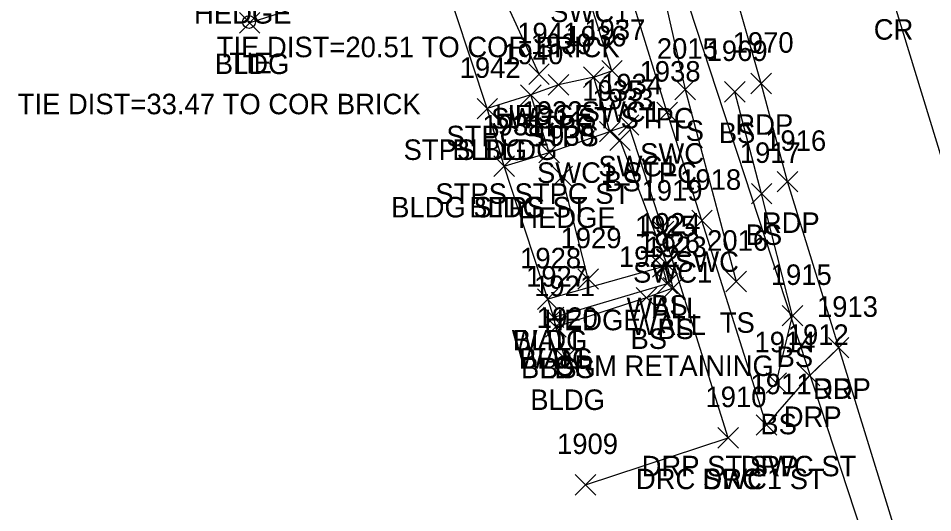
# Model space of a CAD drawing. Extents: x 1620157 to 1620595, y 115111 to 117885.
# Drawn here: x 1620162.6 to 1620251.8, y 115651.9 to 115700.1 of the extents above; entities that cross this region are included whole.
import ezdxf

# ---------------------------------------------------------------- set-up
doc = ezdxf.new("R2010")
doc.units = 0
for name, color, linetype in [('C_A', 7, 'Continuous'), ('C_C', 7, 'Continuous'), ('CBP', 7, 'Continuous'), ('DCP', 7, 'Continuous'), ('L_A', 7, 'Continuous'), ('L_C', 7, 'Continuous'), ('L_I', 7, 'Continuous'), ('L_TIC', 7, 'Continuous'), ('LAHR', 7, 'Continuous'), ('LBC', 7, 'Continuous'), ('LBF', 7, 'Continuous'), ('LELB', 7, 'Continuous'), ('LW', 7, 'Continuous'), ('P_A', 7, 'Continuous'), ('P_I', 7, 'Continuous'), ('P_TIC', 7, 'Continuous'), ('PET', 7, 'Continuous'), ('PRC', 7, 'Continuous'), ('R_A', 7, 'Continuous'), ('R_I', 7, 'Continuous'), ('R_TIC', 7, 'Continuous'), ('RDP', 7, 'Continuous'), ('RSW', 7, 'Continuous')]:
    doc.layers.add(name, color=color, linetype=linetype)

msp = doc.modelspace()

# ---------------------------------------------------------------- linework, layer by layer
at = {"layer": 'CBP'}
for radius in [0.625, 0.0833]:
    msp.add_circle((1620185.129, 115699.764), radius, dxfattribs=at)
at = {"layer": 'DCP'}
msp.add_lwpolyline([(1620265.107, 115588.482), (1620223.378, 115715.616)], dxfattribs=at)
at = {"layer": 'L_TIC'}
for points in [[(1620184.195, 115698.683), (1620186.195, 115700.683)], [(1620186.195, 115698.683), (1620184.195, 115700.683)], [(1620212.417, 115693.681), (1620214.417, 115695.681)], [(1620214.417, 115693.681), (1620212.417, 115695.681)], [(1620217.753, 115693.378), (1620219.753, 115695.378)], [(1620219.753, 115693.378), (1620217.753, 115695.378)], [(1620214.313, 115692.628), (1620216.313, 115694.628)], [(1620216.313, 115692.628), (1620214.313, 115694.628)], [(1620226.682, 115692.172), (1620228.682, 115694.172)], [(1620228.682, 115692.172), (1620226.682, 115694.172)], [(1620231.511, 115691.955), (1620233.511, 115693.955)], [(1620233.511, 115691.955), (1620231.511, 115693.955)], [(1620211.618, 115691.643), (1620213.618, 115693.643)], [(1620213.618, 115691.643), (1620211.618, 115693.643)], [(1620211.618, 115691.643), (1620213.618, 115693.643)], [(1620213.618, 115691.643), (1620211.618, 115693.643)], [(1620207.37, 115690.31), (1620209.37, 115692.31)], [(1620209.37, 115690.31), (1620207.37, 115692.31)], [(1620207.37, 115690.31), (1620209.37, 115692.31)], [(1620209.37, 115690.31), (1620207.37, 115692.31)], [(1620219.331, 115688.074), (1620221.331, 115690.074)], [(1620221.331, 115688.074), (1620219.331, 115690.074)], [(1620220.32, 115687.244), (1620222.32, 115689.244)], [(1620222.32, 115687.244), (1620220.32, 115689.244)], [(1620213.414, 115686.031), (1620215.414, 115688.031)], [(1620215.414, 115686.031), (1620213.414, 115688.031)], [(1620213.414, 115686.031), (1620215.414, 115688.031)], [(1620215.414, 115686.031), (1620213.414, 115688.031)], [(1620209.026, 115684.705), (1620211.026, 115686.705)], [(1620211.026, 115684.705), (1620209.026, 115686.705)], [(1620209.026, 115684.705), (1620211.026, 115686.705)], [(1620211.026, 115684.705), (1620209.026, 115686.705)], [(1620214.691, 115683.69), (1620216.691, 115685.69)], [(1620216.691, 115683.69), (1620214.691, 115685.69)], [(1620234.13, 115682.022), (1620236.13, 115684.022)], [(1620236.13, 115682.022), (1620234.13, 115684.022)], [(1620224.478, 115674.876), (1620226.478, 115676.876)], [(1620226.478, 115674.876), (1620224.478, 115676.876)], [(1620224.478, 115674.876), (1620226.478, 115676.876)], [(1620226.478, 115674.876), (1620224.478, 115676.876)], [(1620224.906, 115675.132), (1620226.906, 115677.132)], [(1620226.906, 115675.132), (1620224.906, 115677.132)], [(1620217.217, 115673.706), (1620219.217, 115675.706)], [(1620219.217, 115673.706), (1620217.217, 115675.706)], [(1620224.923, 115673.246), (1620226.923, 115675.246)], [(1620226.923, 115673.246), (1620224.923, 115675.246)], [(1620231.641, 115673.457), (1620233.641, 115675.457)], [(1620233.641, 115673.457), (1620231.641, 115675.457)], [(1620225.517, 115672.845), (1620227.517, 115674.845)], [(1620227.517, 115672.845), (1620225.517, 115674.845)], [(1620213.268, 115671.742), (1620215.268, 115673.742)], [(1620215.268, 115671.742), (1620213.268, 115673.742)], [(1620213.268, 115671.742), (1620215.268, 115673.742)], [(1620215.268, 115671.742), (1620213.268, 115673.742)], [(1620222.902, 115671.883), (1620224.902, 115673.883)], [(1620224.902, 115671.883), (1620222.902, 115673.883)], [(1620213.849, 115669.959), (1620215.849, 115671.959)], [(1620215.849, 115669.959), (1620213.849, 115671.959)], [(1620213.849, 115669.959), (1620215.849, 115671.959)], [(1620215.849, 115669.959), (1620213.849, 115671.959)], [(1620237.148, 115670.123), (1620239.148, 115672.123)], [(1620239.148, 115670.123), (1620237.148, 115672.123)], [(1620214.066, 115669.033), (1620216.066, 115671.033)], [(1620216.066, 115669.033), (1620214.066, 115671.033)], [(1620214.066, 115669.033), (1620216.066, 115671.033)], [(1620216.066, 115669.033), (1620214.066, 115671.033)], [(1620214.975, 115665.935), (1620216.975, 115667.935)], [(1620216.975, 115665.935), (1620214.975, 115667.935)], [(1620235.562, 115663.561), (1620237.562, 115665.561)], [(1620237.562, 115663.561), (1620235.562, 115665.561)]]:
    msp.add_lwpolyline(points, dxfattribs=at)
at = {"layer": 'LAHR'}
for points in [[(1620213.417, 115694.681), (1620206.467, 115709.825), (1620184.063, 115704.598)], [(1620218.217, 115674.706), (1620215.691, 115684.69)]]:
    msp.add_lwpolyline(points, dxfattribs=at)
at = {"layer": 'LBC'}
msp.add_lwpolyline([(1620215.975, 115666.935), (1620215.066, 115670.033), (1620214.849, 115670.959), (1620214.268, 115672.742), (1620210.026, 115685.705), (1620208.37, 115691.31), (1620203.654, 115705.592), (1620185.195, 115699.683)], dxfattribs=at)
at = {"layer": 'LBF'}
for points in [[(1620214.414, 115687.031), (1620220.331, 115689.074), (1620218.753, 115694.378), (1620215.313, 115693.628), (1620212.618, 115692.643)], [(1620210.026, 115685.705), (1620214.414, 115687.031), (1620212.618, 115692.643), (1620208.37, 115691.31)]]:
    msp.add_lwpolyline(points, dxfattribs=at)
at = {"layer": 'LELB'}
for points in [[(1620197.795, 115734.316), (1620202.944, 115732.819), (1620211.98, 115722.576), (1620224.178, 115708.712), (1620227.682, 115693.172), (1620232.641, 115674.457)], [(1620236.562, 115664.561), (1620238.148, 115671.123), (1620235.13, 115683.022), (1620232.511, 115692.955)], [(1620215.066, 115670.033), (1620223.902, 115672.883), (1620226.517, 115673.845), (1620225.906, 115676.132), (1620221.32, 115688.244)]]:
    msp.add_lwpolyline(points, dxfattribs=at)
at = {"layer": 'LW'}
for points in [[(1620225.478, 115675.876), (1620214.268, 115672.742)], [(1620225.478, 115675.876), (1620225.923, 115674.246), (1620214.849, 115670.959)]]:
    msp.add_lwpolyline(points, dxfattribs=at)
at = {"layer": 'P_TIC'}
for points in [[(1620234.083, 115692.763), (1620236.083, 115694.763)], [(1620236.083, 115692.763), (1620234.083, 115694.763)], [(1620236.662, 115683.194), (1620238.662, 115685.194)], [(1620238.662, 115683.194), (1620236.662, 115685.194)], [(1620241.654, 115667.014), (1620243.654, 115669.014)], [(1620243.654, 115667.014), (1620241.654, 115669.014)]]:
    msp.add_lwpolyline(points, dxfattribs=at)
at = {"layer": 'PET'}
msp.add_lwpolyline([(1620320.138, 115439.395), (1620314.873, 115455.055), (1620309.06, 115464.385), (1620304.219, 115479.395), (1620297.094, 115496.088), (1620293.948, 115506.925), (1620292.02, 115512.471), (1620283.673, 115536.019), (1620274.577, 115564.814), (1620268.484, 115584.523), (1620253.11, 115635.23), (1620250.119, 115643.884), (1620242.654, 115668.014), (1620237.662, 115684.194), (1620235.083, 115693.763), (1620231.193, 115707.415), (1620225.409, 115727.426), (1620211.93, 115771.954), (1620203.83, 115799.038), (1620193.365, 115837.216)], dxfattribs=at)
at = {"layer": 'PRC'}
msp.add_lwpolyline([(1620328.083, 115447.457), (1620322.143, 115466.609), (1620311.316, 115499.812), (1620303.781, 115522.909), (1620294.725, 115551.741), (1620279.311, 115600.233), (1620271.119, 115626.45), (1620257.914, 115669.486), (1620247.637, 115703.034), (1620242.452, 115719.653), (1620232.976, 115752.347), (1620223.662, 115784.044), (1620214.136, 115816.154), (1620207.469, 115841.181)], dxfattribs=at)
at = {"layer": 'R_TIC'}
for points in [[(1620219.531, 115694.011), (1620221.531, 115696.011)], [(1620221.531, 115694.011), (1620219.531, 115696.011)], [(1620217.753, 115693.378), (1620219.753, 115695.378)], [(1620219.753, 115693.378), (1620217.753, 115695.378)], [(1620224.918, 115689.945), (1620226.918, 115691.945)], [(1620226.918, 115689.945), (1620224.918, 115691.945)], [(1620221.168, 115688.711), (1620223.168, 115690.711)], [(1620223.168, 115688.711), (1620221.168, 115690.711)], [(1620219.331, 115688.074), (1620221.331, 115690.074)], [(1620221.331, 115688.074), (1620219.331, 115690.074)], [(1620228.313, 115679.398), (1620230.313, 115681.398)], [(1620230.313, 115679.398), (1620228.313, 115681.398)], [(1620224.553, 115678.345), (1620226.553, 115680.345)], [(1620226.553, 115678.345), (1620224.553, 115680.345)], [(1620241.654, 115667.014), (1620243.654, 115669.014)], [(1620243.654, 115667.014), (1620241.654, 115669.014)], [(1620238.804, 115664.278), (1620240.804, 115666.278)], [(1620240.804, 115664.278), (1620238.804, 115666.278)], [(1620234.608, 115659.465), (1620236.608, 115661.465)], [(1620236.608, 115659.465), (1620234.608, 115661.465)], [(1620234.608, 115659.465), (1620236.608, 115661.465)], [(1620236.608, 115659.465), (1620234.608, 115661.465)], [(1620230.868, 115658.214), (1620232.868, 115660.214)], [(1620232.868, 115658.214), (1620230.868, 115660.214)], [(1620230.868, 115658.214), (1620232.868, 115660.214)], [(1620232.868, 115658.214), (1620230.868, 115660.214)], [(1620216.957, 115653.638), (1620218.957, 115655.638)], [(1620218.957, 115653.638), (1620216.957, 115655.638)]]:
    msp.add_lwpolyline(points, dxfattribs=at)
at = {"layer": 'RDP'}
for points in [[(1620235.608, 115660.465), (1620239.804, 115665.278), (1620242.654, 115668.014)], [(1620217.957, 115654.638), (1620231.868, 115659.214)]]:
    msp.add_lwpolyline(points, dxfattribs=at)
at = {"layer": 'RSW'}
for points in [[(1620235.608, 115660.465), (1620229.313, 115680.398), (1620225.918, 115690.945), (1620221.039, 115706.713), (1620220.247, 115708.993), (1620218.98, 115710.722), (1620216.243, 115713.35), (1620201.579, 115727.899), (1620197.914, 115731.583), (1620194.509, 115734.738), (1620191.974, 115731.835), (1620193.114, 115730.36), (1620193.386, 115728.404), (1620192.886, 115726.516), (1620191.873, 115725.229), (1620181.577, 115715.115)], [(1620218.753, 115694.378), (1620220.531, 115695.011), (1620217.463, 115704.749), (1620216.711, 115706.635), (1620215.582, 115708.467), (1620200.617, 115722.765), (1620199.917, 115723.615), (1620198.61, 115723.85), (1620197.008, 115723.537), (1620181.568, 115708.398)], [(1620231.868, 115659.214), (1620225.553, 115679.345), (1620222.168, 115689.711), (1620220.331, 115689.074)]]:
    msp.add_lwpolyline(points, dxfattribs=at)

# ---------------------------------------------------------------- texts
at = {"layer": 'C_A'}
msp.add_text('TIE', height=2, dxfattribs=at).set_placement((1620183.208, 115694.764))
at = {"layer": 'C_C'}
for s, p in [('TIE DIST=20.51 TO COR BRICK', (1620181.975, 115696.323)), ('TIE DIST=33.47 TO COR BRICK', (1620162.563, 115690.764))]:
    msp.add_text(s, height=2, dxfattribs=at).set_placement(p)
at = {"layer": 'L_A'}
for s, p in [('HEDGE', (1620179.764, 115699.598)), ('BLDG', (1620181.786, 115694.683)), ('SWC1 ST STPC', (1620208.745, 115689.378)), ('HEDGE', (1620209.118, 115689.681)), ('STPC', (1620211.825, 115688.628)), ('STPC STPS', (1620204.382, 115687.643)), ('STPC STPS', (1620204.382, 115687.643)), ('TS', (1620226.091, 115688.172)), ('BS', (1620230.952, 115687.955)), ('STPS BLDG', (1620200.204, 115686.31)), ('BLDG', (1620204.96, 115686.31)), ('SWC1 STPC', (1620213.221, 115684.074)), ('BS', (1620219.761, 115683.244)), ('STPS STPC ST', (1620203.303, 115682.031)), ('STPS STPC ST', (1620203.303, 115682.031)), ('BLDG STPS ST', (1620198.994, 115680.705)), ('BLDG', (1620206.616, 115680.705)), ('HEDGE', (1620211.392, 115679.69)), ('BS', (1620233.571, 115678.022)), ('WALL', (1620221.966, 115670.876)), ('WALL', (1620221.966, 115670.876)), ('BS', (1620224.347, 115671.132)), ('HEDGE', (1620213.918, 115669.706)), ('WALL', (1620222.411, 115669.246)), ('BS', (1620224.958, 115668.845)), ('TS', (1620231.051, 115669.457)), ('WALL', (1620210.756, 115667.742)), ('BLDG', (1620210.859, 115667.742)), ('BS', (1620222.343, 115667.883)), ('WALL', (1620211.337, 115665.959)), ('BLDG', (1620211.439, 115665.959)), ('BS', (1620236.589, 115666.123)), ('BLDG', (1620211.657, 115665.033)), ('BS', (1620213.507, 115665.033)), ('BLDG', (1620212.566, 115661.935)), ('BS', (1620235.003, 115659.561))]:
    msp.add_text(s, height=2, dxfattribs=at).set_placement(p)
at = {"layer": 'L_C'}
msp.add_text('CRM RETAINING', height=2, dxfattribs=at).set_placement((1620214.924, 115665.246))
at = {"layer": 'L_I'}
for s, p in [('1941', (1620211.291, 115697.681)), ('1936', (1620216.005, 115697.378)), ('1939', (1620212.613, 115696.628)), ('1940', (1620209.839, 115695.643)), ('1940', (1620209.839, 115695.643)), ('2015', (1620224.91, 115696.172)), ('1969', (1620229.764, 115695.955)), ('1942', (1620205.677, 115694.31)), ('1942', (1620205.677, 115694.31)), ('1935', (1620217.638, 115692.074)), ('1933', (1620218.627, 115691.244)), ('1932', (1620211.721, 115690.031)), ('1932', (1620211.721, 115690.031)), ('1931', (1620207.9, 115688.705)), ('1931', (1620207.9, 115688.705)), ('1930', (1620212.912, 115687.69)), ('1917', (1620233.004, 115686.022)), ('1925', (1620222.785, 115678.876)), ('1925', (1620222.785, 115678.876)), ('1924', (1620223.213, 115679.132)), ('1929', (1620215.517, 115677.706)), ('1926', (1620223.175, 115677.246)), ('1923', (1620223.824, 115676.845)), ('2016', (1620229.815, 115677.457)), ('1928', (1620211.575, 115675.742)), ('1928', (1620211.575, 115675.742)), ('1922', (1620221.21, 115675.883)), ('1927', (1620212.156, 115673.959)), ('1927', (1620212.156, 115673.959)), ('1915', (1620236.022, 115674.123)), ('1921', (1620212.941, 115673.033)), ('1921', (1620212.941, 115673.033)), ('1920', (1620213.196, 115669.935)), ('1914', (1620234.437, 115667.561))]:
    msp.add_text(s, height=2, dxfattribs=at).set_placement(p)
at = {"layer": 'P_A'}
for s, p in [('CR', (1620246.07, 115698.034)), ('RDP', (1620232.572, 115688.763)), ('RDP', (1620235.15, 115679.194)), ('RDP', (1620240.142, 115663.014))]:
    msp.add_text(s, height=2, dxfattribs=at).set_placement(p)
at = {"layer": 'P_I'}
for s, p in [('1970', (1620232.304, 115696.763)), ('1916', (1620235.481, 115687.194)), ('1913', (1620240.528, 115671.014))]:
    msp.add_text(s, height=2, dxfattribs=at).set_placement(p)
at = {"layer": 'R_A'}
for s, p in [('SWC1', (1620214.503, 115699.749)), ('SWC1', (1620217.57, 115690.011)), ('SWC1 ST STPC', (1620208.745, 115689.378)), ('SWC', (1620223.28, 115685.945)), ('SWC1', (1620219.207, 115684.711)), ('SWC1 STPC', (1620213.221, 115684.074)), ('SWC', (1620226.675, 115675.398)), ('SWC1', (1620222.593, 115674.345)), ('DRP', (1620240.142, 115663.014)), ('DRP', (1620237.293, 115660.278)), ('DRP ST SWC ST', (1620223.427, 115655.465)), ('DRP', (1620233.096, 115655.465)), ('DRC SWC1 ST', (1620222.868, 115654.214)), ('DRC', (1620229.356, 115654.214))]:
    msp.add_text(s, height=2, dxfattribs=at).set_placement(p)
at = {"layer": 'R_I'}
for s, p in [('1936', (1620216.005, 115697.378)), ('1937', (1620217.838, 115698.011)), ('1938', (1620223.225, 115693.945)), ('1934', (1620219.475, 115692.711)), ('1935', (1620217.638, 115692.074)), ('1918', (1620227.188, 115683.398)), ('1919', (1620223.42, 115682.345)), ('1913', (1620240.528, 115671.014)), ('1912', (1620237.679, 115668.278)), ('1911', (1620234.049, 115663.465)), ('1911', (1620234.049, 115663.465)), ('1910', (1620229.655, 115662.214)), ('1910', (1620229.655, 115662.214)), ('1909', (1620215.177, 115657.638))]:
    msp.add_text(s, height=2, dxfattribs=at).set_placement(p)

doc.saveas('drawing.dxf')
